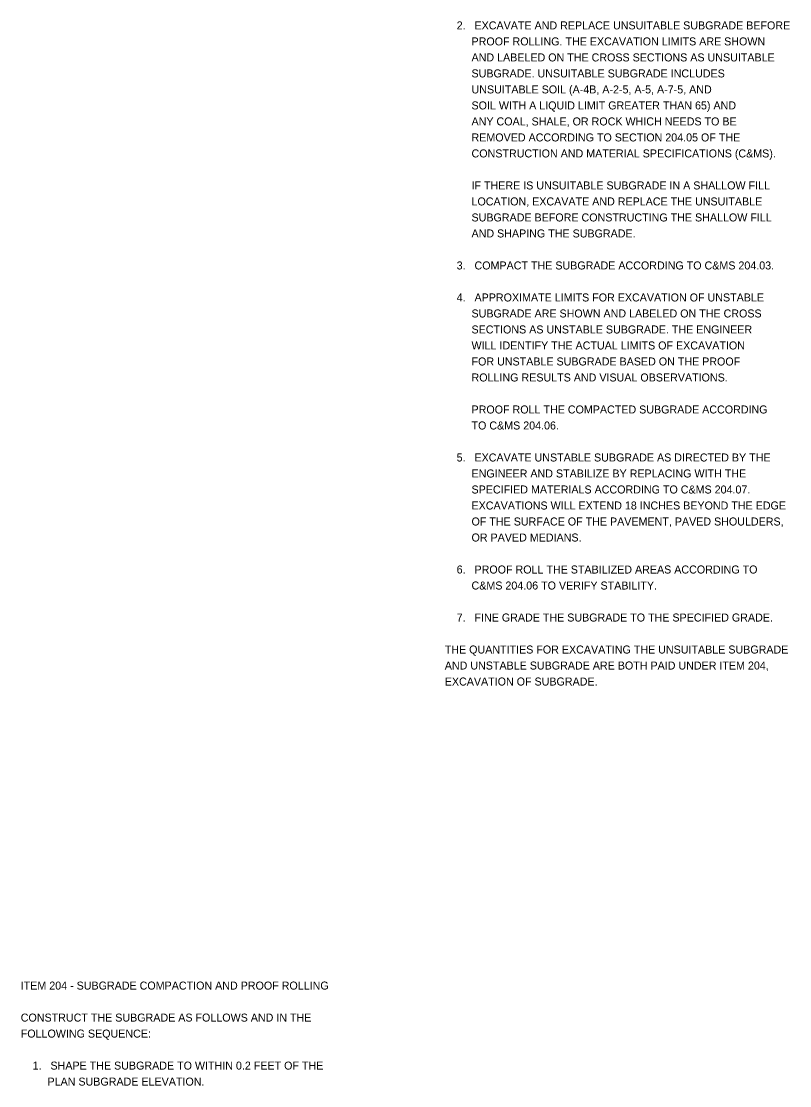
# Model space of a CAD drawing. Extents: x -24.6 to 58.4, y 0 to 22.8.
# Drawn here: x -24.64 to -11.2, y 4.19 to 22.81 of the extents above; entities that cross this region are included whole.
import ezdxf

# ---------------------------------------------------------------- set-up
doc = ezdxf.new("R2010")
doc.units = 0
doc.layers.add('SH_Text', color=7, linetype='Continuous')

msp = doc.modelspace()

# ---------------------------------------------------------------- texts
at = {"layer": 'SH_Text'}
for s, p in [('    2.   EXCAVATE AND REPLACE UNSUITABLE SUBGRADE BEFORE', (-17.232, 22.667)), ('         PROOF ROLLING. THE EXCAVATION LIMITS ARE SHOWN', (-17.232, 22.387)), ('         AND LABELED ON THE CROSS SECTIONS AS UNSUITABLE', (-17.232, 22.107)), ('         SUBGRADE. UNSUITABLE SUBGRADE INCLUDES', (-17.232, 21.827)), ('         UNSUITABLE SOIL (A-4B, A-2-5, A-5, A-7-5, AND', (-17.232, 21.547)), ('         SOIL WITH A LIQUID LIMIT GREATER THAN 65) AND', (-17.232, 21.267)), ('         ANY COAL, SHALE, OR ROCK WHICH NEEDS TO BE', (-17.232, 20.987)), ('         REMOVED ACCORDING TO SECTION 204.05 OF THE', (-17.232, 20.707)), ('         CONSTRUCTION AND MATERIAL SPECIFICATIONS (C&MS).', (-17.232, 20.427)), ('         IF THERE IS UNSUITABLE SUBGRADE IN A SHALLOW FILL', (-17.232, 19.867)), ('         LOCATION, EXCAVATE AND REPLACE THE UNSUITABLE', (-17.232, 19.587)), ('         SUBGRADE BEFORE CONSTRUCTING THE SHALLOW FILL', (-17.232, 19.307)), ('         AND SHAPING THE SUBGRADE.', (-17.232, 19.027)), ('    3.   COMPACT THE SUBGRADE ACCORDING TO C&MS 204.03.', (-17.232, 18.467)), ('    4.   APPROXIMATE LIMITS FOR EXCAVATION OF UNSTABLE', (-17.232, 17.907)), ('         SUBGRADE ARE SHOWN AND LABELED ON THE CROSS', (-17.232, 17.627)), ('         SECTIONS AS UNSTABLE SUBGRADE. THE ENGINEER', (-17.232, 17.347)), ('         WILL IDENTIFY THE ACTUAL LIMITS OF EXCAVATION', (-17.232, 17.067)), ('         FOR UNSTABLE SUBGRADE BASED ON THE PROOF', (-17.232, 16.787)), ('         ROLLING RESULTS AND VISUAL OBSERVATIONS.', (-17.232, 16.507)), ('         PROOF ROLL THE COMPACTED SUBGRADE ACCORDING', (-17.232, 15.947)), ('         TO C&MS 204.06.', (-17.232, 15.667)), ('    5.   EXCAVATE UNSTABLE SUBGRADE AS DIRECTED BY THE', (-17.232, 15.107)), ('         ENGINEER AND STABILIZE BY REPLACING WITH THE', (-17.232, 14.827)), ('         SPECIFIED MATERIALS ACCORDING TO C&MS 204.07.', (-17.232, 14.547)), ('         EXCAVATIONS WILL EXTEND 18 INCHES BEYOND THE EDGE', (-17.232, 14.267)), ('         OF THE SURFACE OF THE PAVEMENT, PAVED SHOULDERS,', (-17.232, 13.987)), ('         OR PAVED MEDIANS.', (-17.232, 13.707)), ('    6.   PROOF ROLL THE STABILIZED AREAS ACCORDING TO', (-17.232, 13.147)), ('         C&MS 204.06 TO VERIFY STABILITY.', (-17.232, 12.867)), ('    7.   FINE GRADE THE SUBGRADE TO THE SPECIFIED GRADE.', (-17.232, 12.307)), ('THE QUANTITIES FOR EXCAVATING THE UNSUITABLE SUBGRADE', (-17.232, 11.747)), ('AND UNSTABLE SUBGRADE ARE BOTH PAID UNDER ITEM 204,', (-17.232, 11.467)), ('EXCAVATION OF SUBGRADE.', (-17.232, 11.187)), ('ITEM 204 - SUBGRADE COMPACTION AND PROOF ROLLING', (-24.652, 5.867)), ('CONSTRUCT THE SUBGRADE AS FOLLOWS AND IN THE', (-24.652, 5.307)), ('FOLLOWING SEQUENCE:', (-24.652, 5.027)), ('    1.   SHAPE THE SUBGRADE TO WITHIN 0.2 FEET OF THE', (-24.652, 4.467)), ('         PLAN SUBGRADE ELEVATION.', (-24.652, 4.187))]:
    msp.add_text(s, height=0.14, dxfattribs=at).set_placement(p)

doc.saveas('drawing.dxf')
